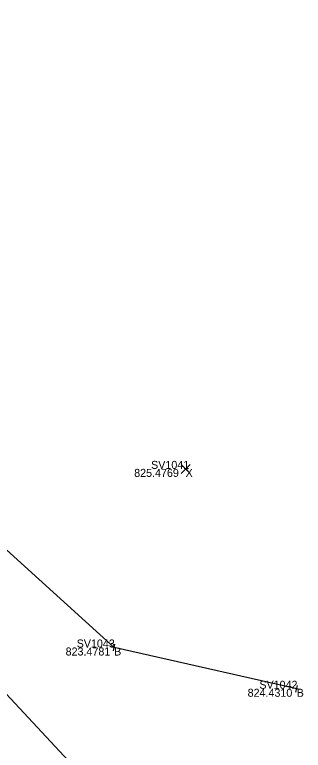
# Model space of a CAD drawing. Extents: x 1715717 to 1717046, y 393954 to 396000.
# Drawn here: x 1716296.2 to 1716317.8, y 394692.5 to 394747.6 of the extents above; entities that cross this region are included whole.
import ezdxf

# ---------------------------------------------------------------- set-up
doc = ezdxf.new("R2010")
doc.units = 0
for name, color, linetype in [('DR_X_Ditch', 7, 'Continuous'), ('SV_X_Break_Lines', 7, 'Continuous'), ('SV_X_Random_Point', 7, 'Continuous'), ('SV_X_Shot_Marker', 7, 'Continuous'), ('SV_X_Text_Comment', 7, 'Continuous'), ('SV_X_Text_Elevation', 7, 'Continuous'), ('SV_X_Text_Name', 7, 'Continuous')]:
    doc.layers.add(name, color=color, linetype=linetype)

msp = doc.modelspace()

# ---------------------------------------------------------------- linework, layer by layer
at = {"layer": 'DR_X_Ditch'}
msp.add_lwpolyline([(1716258.193, 394735.329), (1716271.453, 394720.588), (1716281.209, 394710.734), (1716293.883, 394698.528), (1716301.253, 394690.647), (1716306.847, 394681.776)], dxfattribs=at)
at = {"layer": 'SV_X_Break_Lines'}
msp.add_lwpolyline([(1716317.343, 394697.112), (1716303.665, 394700.204), (1716293.428, 394709.483), (1716278.921, 394722.479), (1716263.167, 394736.839), (1716279.618, 394747.622)], dxfattribs=at)
at = {"layer": 'SV_X_Random_Point'}
for p, q in [((1716308.688, 394713.254), (1716309.354, 394713.921)), ((1716308.688, 394713.921), (1716309.354, 394713.254))]:
    msp.add_line(p, q, dxfattribs=at)
at = {"layer": 'SV_X_Shot_Marker'}
for p, q in [((1716303.61, 394699.96), (1716303.72, 394700.448)), ((1716303.909, 394700.149), (1716303.421, 394700.259)), ((1716303.665, 394700.204), (1716303.665, 394700.204)), ((1716317.587, 394697.057), (1716317.1, 394697.168)), ((1716317.288, 394696.869), (1716317.399, 394697.356)), ((1716317.343, 394697.112), (1716317.343, 394697.112))]:
    msp.add_line(p, q, dxfattribs=at)

# ---------------------------------------------------------------- texts
at = {"layer": 'SV_X_Text_Comment'}
for s, p in [('X', (1716309.021, 394712.988)), ('B', (1716303.665, 394699.604)), ('B', (1716317.343, 394696.513))]:
    msp.add_text(s, height=0.6, dxfattribs=at).set_placement(p)
at = {"layer": 'SV_X_Text_Elevation'}
for s, p in [('825.4769', (1716305.171, 394712.988)), ('823.4781', (1716300.037, 394699.604)), ('824.4310', (1716313.668, 394696.513))]:
    msp.add_text(s, height=0.6, dxfattribs=at).set_placement(p)
at = {"layer": 'SV_X_Text_Name'}
for s, p in [('SV1041', (1716306.437, 394713.588)), ('SV1043', (1716300.864, 394700.204)), ('SV1042', (1716314.547, 394697.112))]:
    msp.add_text(s, height=0.6, dxfattribs=at).set_placement(p)

doc.saveas('drawing.dxf')
